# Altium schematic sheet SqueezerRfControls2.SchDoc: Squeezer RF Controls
size C; Organization: LIGO Laboratory; Address1: California Institute of Technology; Address2: Massachusetts Institute of Technology; SheetNumber: 33; SheetTotal: 37; DrawnBy: R.  Abbott; Engineer: R.  Abbott
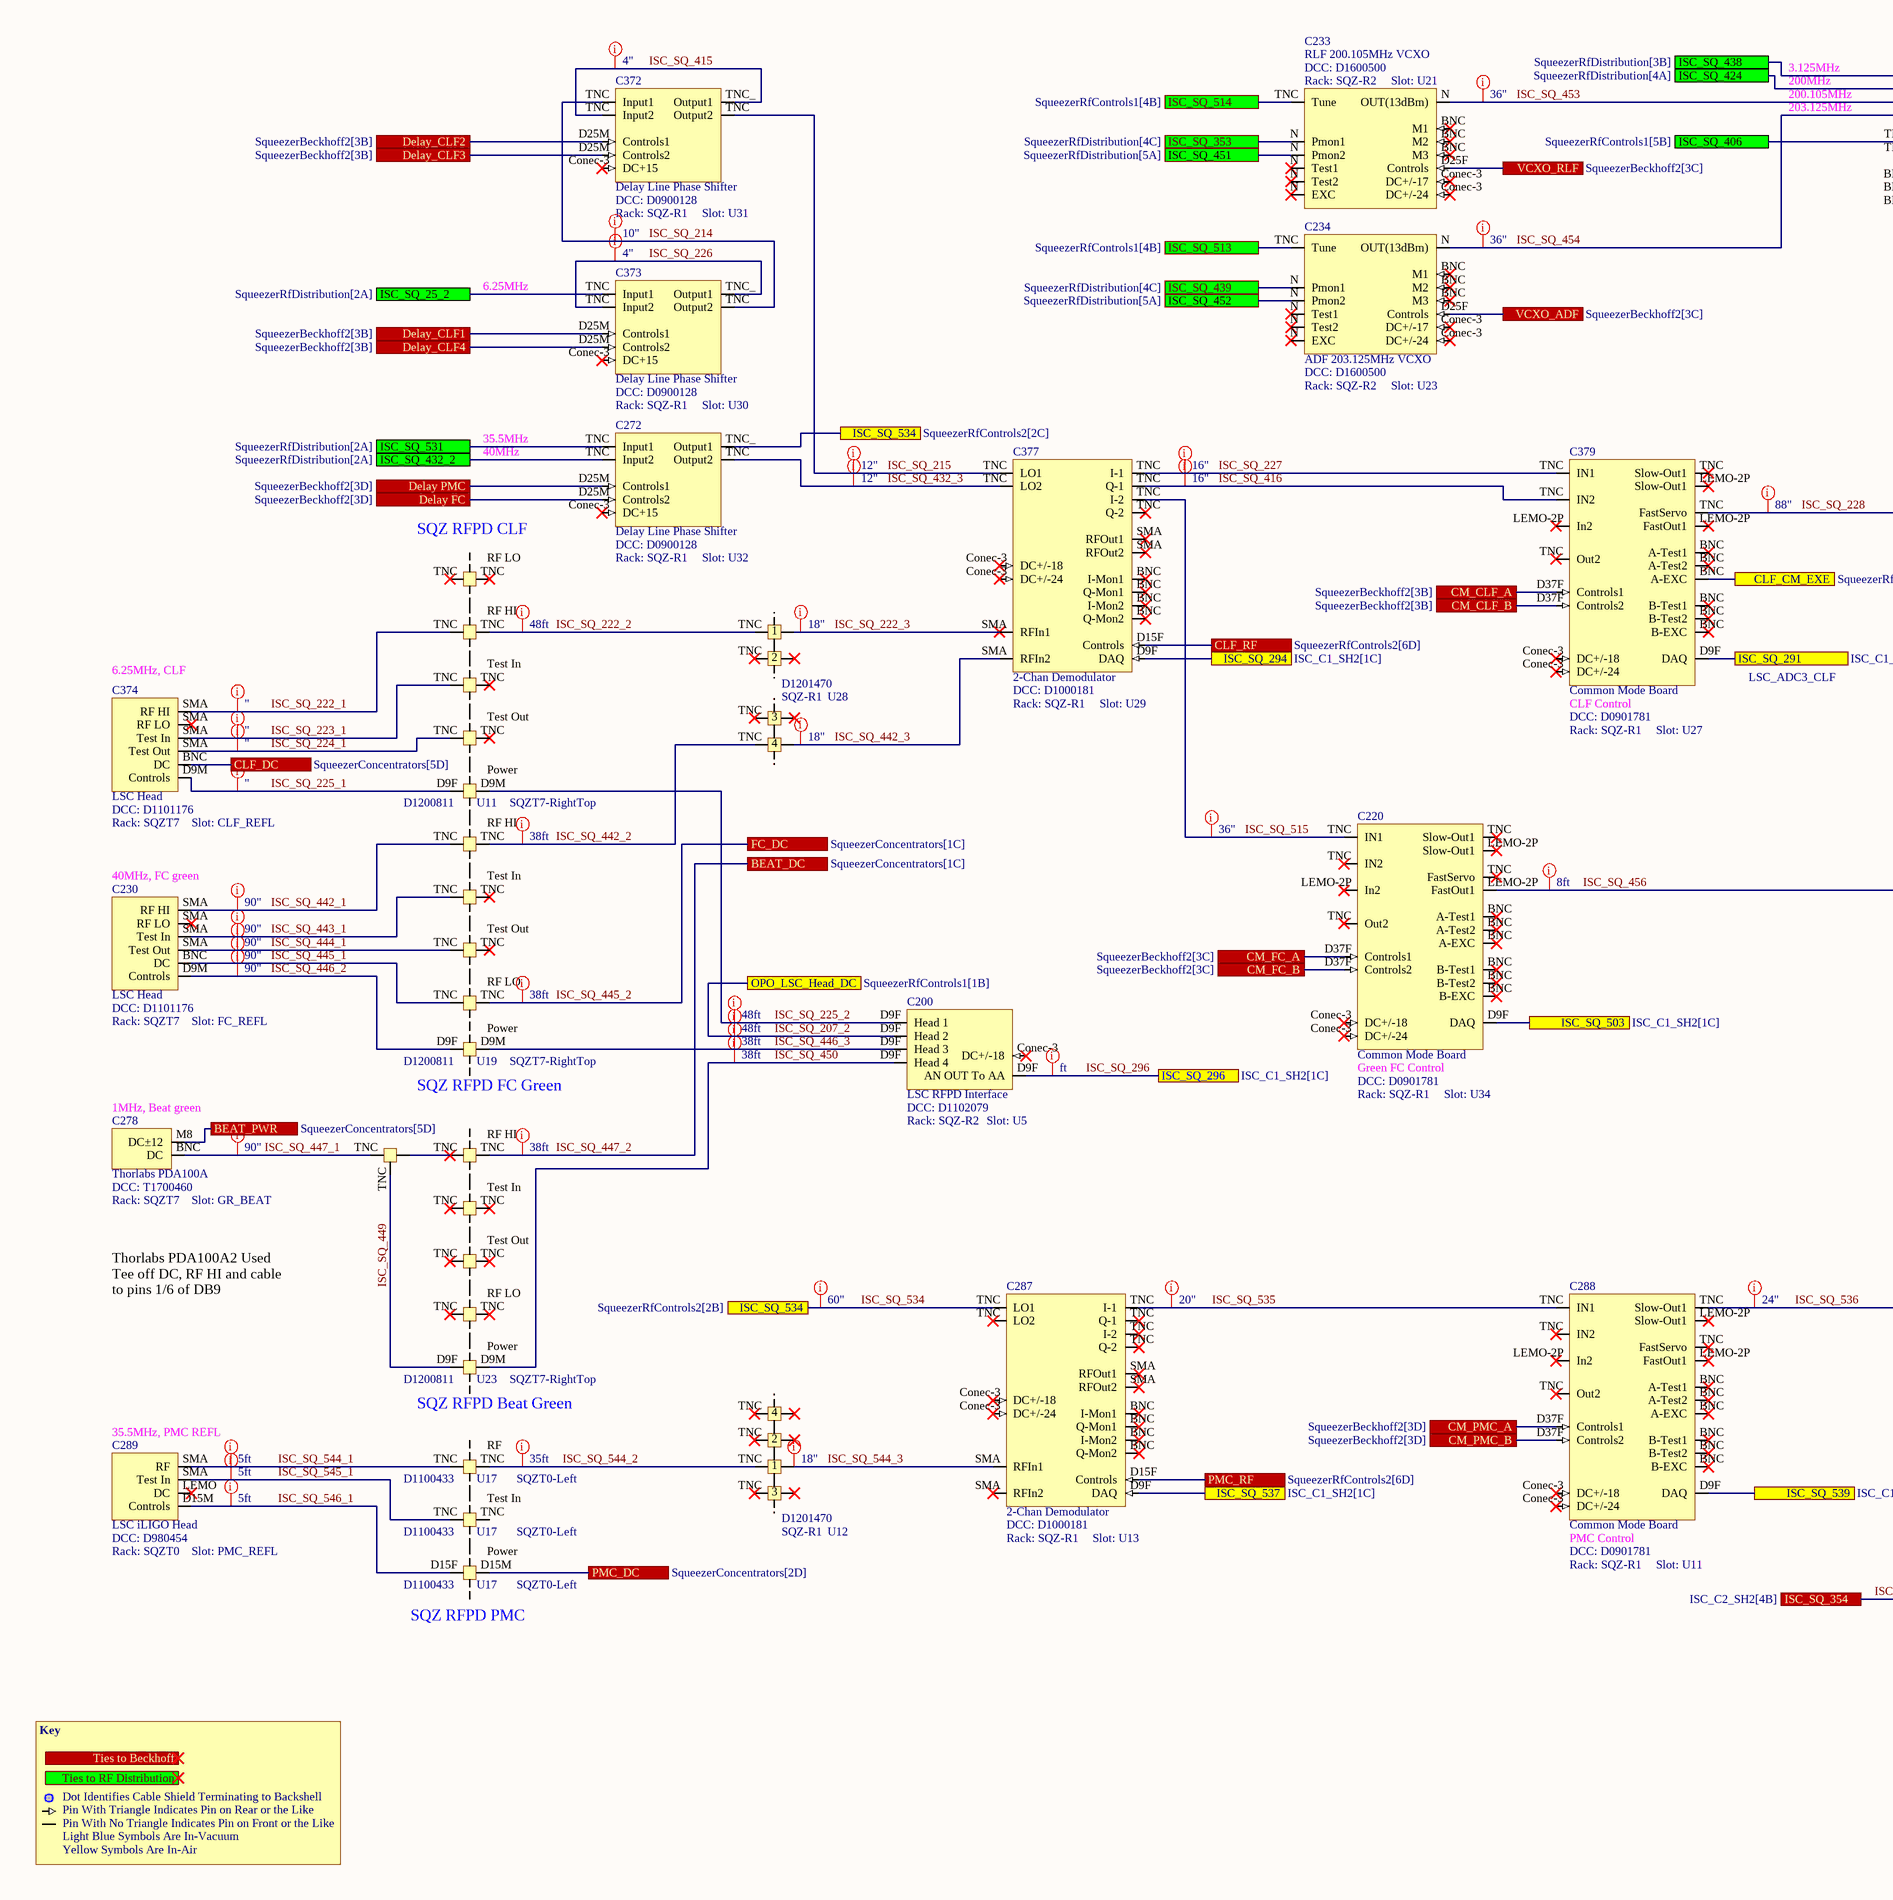
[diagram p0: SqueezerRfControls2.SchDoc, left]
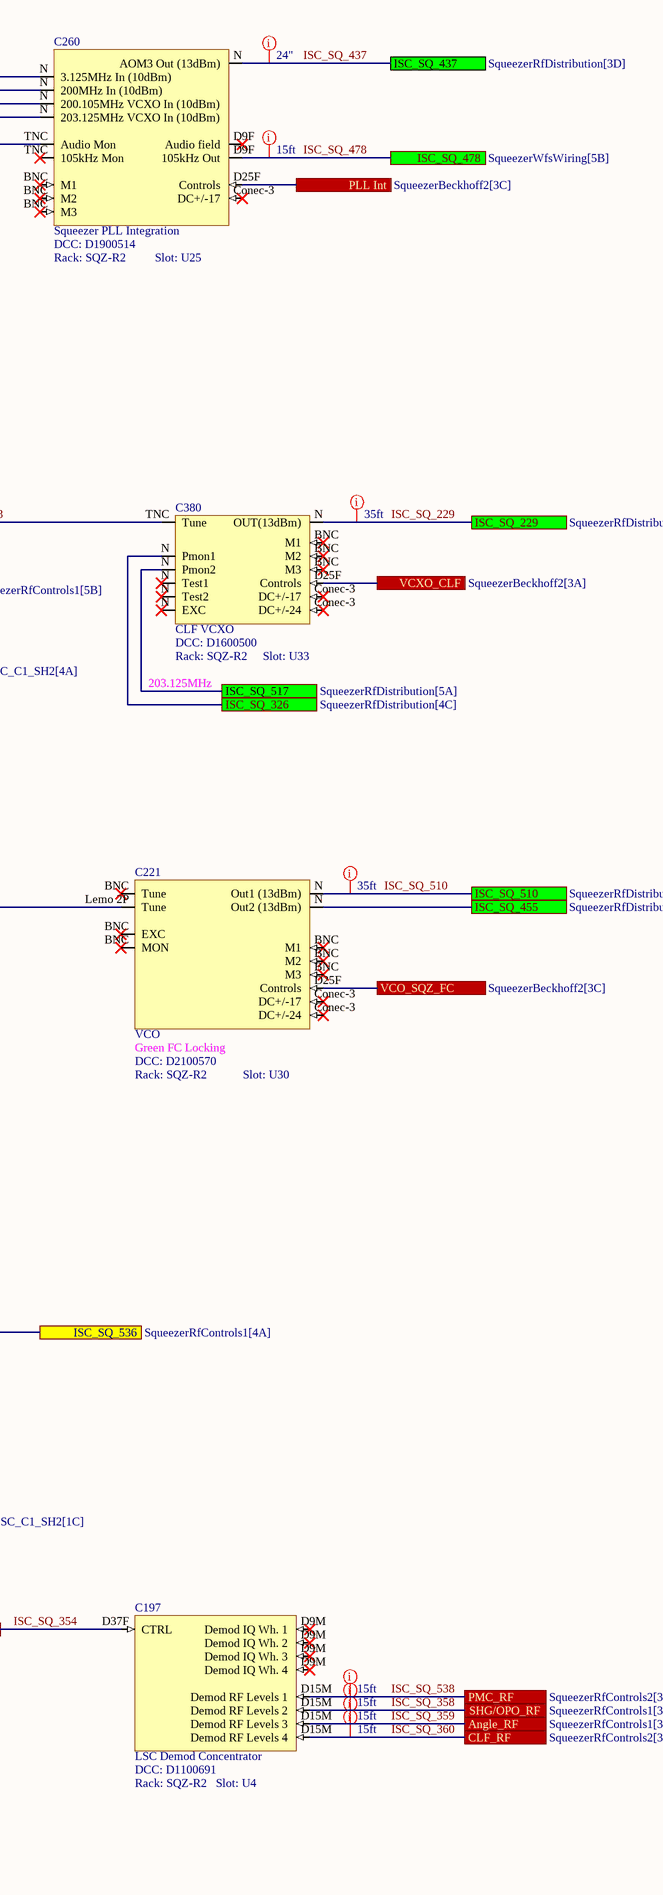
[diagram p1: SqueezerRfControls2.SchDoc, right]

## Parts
(Parts that share a designator on the sheet are numbered #1, #2 ... from top to bottom, then left to right.)
C197  LSC Demod Concentrator  DCC: D1100691  Rack: SQZ-R2  Slot: U4
C200  LSC RFPD Interface  DCC: D1102079  Rack: SQZ-R2  Slot: U5
C220  Common Mode Board  DCC: D0901781  Rack: SQZ-R1  Slot: U34
C221  VCO  DCC: D2100570  Rack: SQZ-R2  Slot: U30
C230  LSC Head  DCC: D1101176  Rack: SQZT7  Slot: FC_REFL
C231  Patch Panel Dual Frequency LSC RFPD  (value not drawn)  (parts A,B,C,D,E of 5)
C233  RLF 200.105MHz VCXO  DCC: D1600500  Rack: SQZ-R2  Slot: U21
C234  ADF 203.125MHz VCXO  DCC: D1600500  Rack: SQZ-R2  Slot: U23
C254  Patch Panel Dual Frequency LSC RFPD  (value not drawn)  (parts A,B,C,D,E of 5)
C260  Squeezer PLL Integration  DCC: D1900514  Rack: SQZ-R2  Slot: U25
C272  Delay Line Phase Shifter  DCC: D0900128  Rack: SQZ-R1  Slot: U32
C278  Thorlabs PDA100A  DCC: T1700460  Rack: SQZT7  Slot: GR_BEAT
C279  Tee  (value not drawn)
C287  2-Chan Demodulator  DCC: D1000181  Rack: SQZ-R1  Slot: U13
C288  Common Mode Board  DCC: D0901781  Rack: SQZ-R1  Slot: U11
C289  LSC iLIGO Head  DCC: D980454  Rack: SQZT0  Slot: PMC_REFL
C290  DCC: D1100433  Rack: SQZT0-Left  Slot: U17  (hidden comment: Patch Panel Legacy iLIGO LSC RFPD)  (parts A,B,C of 3)
C299  Patch Panel TNC 1U  (value not drawn)  (parts A,C of 4)
C372  Delay Line Phase Shifter  DCC: D0900128  Rack: SQZ-R1  Slot: U31
C373  Delay Line Phase Shifter  DCC: D0900128  Rack: SQZ-R1  Slot: U30
C374  LSC Head  DCC: D1101176  Rack: SQZT7  Slot: CLF_REFL
C375  Patch Panel Dual Frequency LSC RFPD  (value not drawn)  (parts A,B,C,D,E of 5)
C376  Patch Panel TNC 1U  (value not drawn)  (parts A,B,C,D of 4)
C377  2-Chan Demodulator  DCC: D1000181  Rack: SQZ-R1  Slot: U29
C379  Common Mode Board  DCC: D0901781  Rack: SQZ-R1  Slot: U27
C380  CLF VCXO  DCC: D1600500  Rack: SQZ-R2  Slot: U33
C?#1  Patch Panel TNC 1U  (value not drawn)  (part D of 4)
C?#2  Patch Panel TNC 1U  (value not drawn)  (part B of 4)

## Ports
Angle_RF (see SqueezerRfControls1[3C]), BEAT_DC (see SqueezerConcentrators[1C]), BEAT_PWR (see SqueezerConcentrators[5D]), CLF_CM_EXE (see SqueezerRfControls1[5B]), CLF_DC (see SqueezerConcentrators[5D]), CLF_RF (see SqueezerRfControls2[3B]), CLF_RF (see SqueezerRfControls2[6D]), CM_CLF_A (see SqueezerBeckhoff2[3B]), CM_CLF_B (see SqueezerBeckhoff2[3B]), CM_FC_A (see SqueezerBeckhoff2[3C]), CM_FC_B (see SqueezerBeckhoff2[3C]), CM_PMC_A (see SqueezerBeckhoff2[3D]), CM_PMC_B (see SqueezerBeckhoff2[3D]), Delay FC (see SqueezerBeckhoff2[3D]), Delay PMC (see SqueezerBeckhoff2[3D]), Delay_CLF1 (see SqueezerBeckhoff2[3B]), Delay_CLF2 (see SqueezerBeckhoff2[3B]), Delay_CLF3 (see SqueezerBeckhoff2[3B]), Delay_CLF4 (see SqueezerBeckhoff2[3B]), FC_DC (see SqueezerConcentrators[1C]), ISC_SQ_25_2 (see SqueezerRfDistribution[2A]), ISC_SQ_229 (see SqueezerRfDistribution[3C]), ISC_SQ_291 (see ISC_C1_SH2[4A]), ISC_SQ_294 (see ISC_C1_SH2[1C]), ISC_SQ_296 (see ISC_C1_SH2[1C]), ISC_SQ_326 (see SqueezerRfDistribution[4C]), ISC_SQ_353 (see SqueezerRfDistribution[4C]), ISC_SQ_354 (see ISC_C2_SH2[4B]), ISC_SQ_406 (see SqueezerRfControls1[5B]), ISC_SQ_424 (see SqueezerRfDistribution[4A]), ISC_SQ_432_2 (see SqueezerRfDistribution[2A]), ISC_SQ_437 (see SqueezerRfDistribution[3D]), ISC_SQ_438 (see SqueezerRfDistribution[3B]), ISC_SQ_439 (see SqueezerRfDistribution[4C]), ISC_SQ_451 (see SqueezerRfDistribution[5A]), ISC_SQ_452 (see SqueezerRfDistribution[5A]), ISC_SQ_455 (see SqueezerRfDistribution[5A]), ISC_SQ_478 (see SqueezerWfsWiring[5B]), ISC_SQ_503 (see ISC_C1_SH2[1C]), ISC_SQ_510 (see SqueezerRfDistribution[3C]), ISC_SQ_513 (see SqueezerRfControls1[4B]), ISC_SQ_514 (see SqueezerRfControls1[4B]), ISC_SQ_517 (see SqueezerRfDistribution[5A]), ISC_SQ_531 (see SqueezerRfDistribution[2A]), ISC_SQ_534 (see SqueezerRfControls2[2B]), ISC_SQ_534 (see SqueezerRfControls2[2C]), ISC_SQ_536 (see SqueezerRfControls1[4A]), ISC_SQ_537 (see ISC_C1_SH2[1C]), ISC_SQ_539 (see ISC_C1_SH2[1C]), OPO_LSC_Head_DC (see SqueezerRfControls1[1B]), PLL Int (see SqueezerBeckhoff2[3C]), PMC_DC (see SqueezerConcentrators[2D]), PMC_RF (see SqueezerRfControls2[3D]), PMC_RF (see SqueezerRfControls2[6D]), SHG/OPO_RF (see SqueezerRfControls1[3B]), Ties to Beckhoff, Ties to RF Distribution, VCO_SQZ_FC (see SqueezerBeckhoff2[3C]), VCXO_ADF (see SqueezerBeckhoff2[3C]), VCXO_CLF (see SqueezerBeckhoff2[3A]), VCXO_RLF (see SqueezerBeckhoff2[3C])

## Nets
BEAT_PWR: C278.M8(DC±12) ; port BEAT_PWR
CLF_CM_EXE: C379.BNC(A-Test1) ; port CLF_CM_EXE
CLF_DC: C374.BNC(DC) ; port CLF_DC
CM_CLF_A: C379.D37F(Controls1) ; port CM_CLF_A
CM_CLF_B: C379.D37F(Controls2) ; port CM_CLF_B
CM_FC_A: C220.D37F(Controls1) ; port CM_FC_A
CM_FC_B: C220.D37F(Controls2) ; port CM_FC_B
CM_PMC_A: C288.D37F(Controls1) ; port CM_PMC_A
CM_PMC_B: C288.D37F(Controls2) ; port CM_PMC_B
Delay FC: C272.D25M(Controls2) ; port Delay FC
Delay PMC: C272.D25M(Controls1) ; port Delay PMC
Delay_CLF1: C373.D25M(Controls1) ; port Delay_CLF1
Delay_CLF2: C372.D25M(Controls1) ; port Delay_CLF2
Delay_CLF3: C372.D25M(Controls2) ; port Delay_CLF3
Delay_CLF4: C373.D25M(Controls2) ; port Delay_CLF4
ISC_SQ_25_2: C373.TNC(Input1) ; port ISC_SQ_25_2
ISC_SQ_207_2: C200.D9F(Head_2) ; port OPO_LSC_Head_DC
ISC_SQ_214: C372.TNC(Input1) C373.TNC(Output2)
ISC_SQ_215: C372.TNC(Output2) C377.TNC(LO1)
ISC_SQ_222_1: C374.SMA(RF_HI) C375.TNC(RFLO)
ISC_SQ_222_2: C375.TNC(RFHI) C376.TNC
ISC_SQ_222_3: C376.TNC C377.SMA(RFOut1)
ISC_SQ_223_1: C374.SMA(Test_In) C375.TNC(TestIn)
ISC_SQ_224_1: C374.SMA(Test_Out) C375.TNC(TestOut)
ISC_SQ_225_1: C374.D9M(Controls) C375.D9F(Power)
ISC_SQ_225_2: C200.D9F(Head_1) C375.D9M(Power)
ISC_SQ_226: C373.TNC(Input2) C373.TNC_(Output1)
ISC_SQ_227: C377.TNC(I-1) C379.TNC(IN1)
ISC_SQ_228: C379.TNC(FastServo) C380.TNC(Tune)
ISC_SQ_229: C380.N(OUT(13dBm)) ; port ISC_SQ_229
ISC_SQ_291: C379.D9F(DAQ) ; port ISC_SQ_291
ISC_SQ_294: C377.D9F(DAQ) ; port ISC_SQ_294
ISC_SQ_296: C200.D9F(AN_OUT_To_AA) ; port ISC_SQ_296
ISC_SQ_326: C380.N(Pmon1) ; port ISC_SQ_326
ISC_SQ_353: C233.N(Pmon1) ; port ISC_SQ_353
ISC_SQ_354: C197.D37F(CTRL) ; port ISC_SQ_354
ISC_SQ_358: C197.D15M(Demod_RF_Levels_2) ; port SHG/OPO_RF
ISC_SQ_359: C197.D15M(Demod_RF_Levels_3) ; port Angle_RF
ISC_SQ_360: C197.D15M(Demod_RF_Levels_4) C377.D15F(Controls) ; port CLF_RF
ISC_SQ_406: C260.TNC(Audio_Mon) ; port ISC_SQ_406
ISC_SQ_415: C372.TNC(Input2) C372.TNC_(Output1)
ISC_SQ_416: C377.TNC(Q-1) C379.TNC(IN2)
ISC_SQ_424: C260.N(200MHz_In_(10dBm)) ; port ISC_SQ_424
ISC_SQ_432_2: C272.TNC(Input2) ; port ISC_SQ_432_2
ISC_SQ_432_3: C272.TNC(Output2) C377.TNC(LO2)
ISC_SQ_437: C260.N(AOM3_Out_(13dBm)) ; port ISC_SQ_437
ISC_SQ_438: C260.N(3.125MHz_In_(10dBm)) ; port ISC_SQ_438
ISC_SQ_439: C234.N(Pmon1) ; port ISC_SQ_439
ISC_SQ_442_1: C230.SMA(RF_HI) C231.TNC(RFHI)
ISC_SQ_442_2: C231.TNC(RFHI) C376.TNC
ISC_SQ_442_3: C376.TNC C377.SMA(RFIn2)
ISC_SQ_443_1: C230.SMA(Test_In) C231.TNC(TestIn)
ISC_SQ_444_1: C230.SMA(Test_Out) C231.TNC(TestOut)
ISC_SQ_445_1: C230.BNC(DC) C231.TNC(RFLO)
ISC_SQ_445_2: C231.TNC(RFLO) ; port FC_DC
ISC_SQ_446_2: C230.D9M(Controls) C231.D9F(Power)
ISC_SQ_446_3: C200.D9F(Head_3) C231.D9M(Power)
ISC_SQ_447_1: C278.BNC(DC) C279.TNC
ISC_SQ_447_2: C254.TNC(RFHI) ; port BEAT_DC
ISC_SQ_449: C254.D9F(Power) C279.TNC
ISC_SQ_450: C200.D9F(Head_4) C254.D9M(Power)
ISC_SQ_451: C233.N(Pmon2) ; port ISC_SQ_451
ISC_SQ_452: C234.N(Pmon2) ; port ISC_SQ_452
ISC_SQ_453: C233.N(OUT(13dBm)) C260.N(200.105MHz_VCXO_In_(10dBm))
ISC_SQ_454: C234.N(OUT(13dBm)) C260.N(203.125MHz_VCXO_In_(10dBm))
ISC_SQ_455: C221.N(Out2_(13dBm)) ; port ISC_SQ_455
ISC_SQ_456: C220.LEMO-2P(In2) C221.Lemo_2P(Tune)
ISC_SQ_478: C260.D9F(105kHz_Out) ; port ISC_SQ_478
ISC_SQ_503: C220.D9F(DAQ) ; port ISC_SQ_503
ISC_SQ_510: C221.N(Out1_(13dBm)) ; port ISC_SQ_510
ISC_SQ_513: C234.TNC(Tune) ; port ISC_SQ_513
ISC_SQ_514: C233.TNC(Tune) ; port ISC_SQ_514
ISC_SQ_515: C220.TNC(IN1) C377.TNC(I-2)
ISC_SQ_517: C380.N(Pmon2) ; port ISC_SQ_517
ISC_SQ_531: C272.TNC(Input1) ; port ISC_SQ_531
ISC_SQ_534: C272.TNC_(Output1) C287.TNC(LO1) ; port ISC_SQ_534
ISC_SQ_535: C287.TNC(I-1) C288.TNC(IN1)
ISC_SQ_536: C288.TNC(Slow-Out1) ; port ISC_SQ_536
ISC_SQ_537: C287.D9F(DAQ) ; port ISC_SQ_537
ISC_SQ_538: C197.D15M(Demod_RF_Levels_1) C287.D15F(Controls) ; port PMC_RF
ISC_SQ_539: C288.D9F(DAQ) ; port ISC_SQ_539
ISC_SQ_544_1: C289.SMA(RF) C290.TNC(RFHI)
ISC_SQ_544_2: C290.TNC(RFHI) C299.TNC
ISC_SQ_544_3: C287.SMA(RFOut1) C299.TNC
ISC_SQ_545_1: C289.SMA(Test_In) C290.TNC(TestIn)
ISC_SQ_546_1: C289.D15M(Controls) C290.D15F(Power)
PLL Int: C260.D25F(Controls) ; port PLL Int
PMC_DC: C290.D15M(Power) ; port PMC_DC
VCO_SQZ_FC: C221.D25F(Controls) ; port VCO_SQZ_FC
VCXO_ADF: C234.D25F(Controls) ; port VCXO_ADF
VCXO_CLF: C380.D25F(Controls) ; port VCXO_CLF
VCXO_RLF: C233.D25F(Controls) ; port VCXO_RLF
NetC254_TNC: C254.TNC(RFLO) C279.TNC

Not connected (* = marked no-connect by the designer): C197 D9M(Demod_IQ_Wh._1)*; C200 Conec-3(DC+/-18)*; C220 BNC(A-Test1)* Conec-3(DC+/-18)*; C221 BNC(Tune)* Conec-3(DC+/-17)*; C233 BNC(M1)* Conec-3(DC+/-17)*; C234 BNC(M1)* Conec-3(DC+/-17)*; C260 BNC(M1)* Conec-3(DC+/-17)*; C272 Conec-3(DC+15)*; C287 BNC(I-Mon1)* Conec-3(DC+/-18)*; C288 BNC(A-Test1)* Conec-3(DC+/-18)* LEMO-2P(In2)*; C289 LEMO(DC)*; C372 Conec-3(DC+15)*; C373 Conec-3(DC+15)*; C377 BNC(I-Mon1)* Conec-3(DC+/-18)*; C379 Conec-3(DC+/-18)* LEMO-2P(In2)*; C380 BNC(M1)* Conec-3(DC+/-17)*; C?#1 TNC(4)*; C?#2 TNC(2)*

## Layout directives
Length: ": ISC_SQ_222_1, ISC_SQ_223_1, ISC_SQ_224_1, ISC_SQ_225_1
Length: 48ft: ISC_SQ_207_2, ISC_SQ_222_2, ISC_SQ_225_2
Length: 16": ISC_SQ_227, ISC_SQ_416
Length: 88": ISC_SQ_228
Length: 35ft: ISC_SQ_229, ISC_SQ_510, ISC_SQ_544_2
Length: 10": ISC_SQ_214
Length: 4": ISC_SQ_226, ISC_SQ_415
Length: 18": ISC_SQ_222_3, ISC_SQ_442_3, ISC_SQ_544_3
Length: 12": ISC_SQ_215, ISC_SQ_432_3
Length: 90": ISC_SQ_442_1, ISC_SQ_443_1, ISC_SQ_444_1, ISC_SQ_445_1, ISC_SQ_446_2, ISC_SQ_447_1
Length: 38ft: ISC_SQ_442_2, ISC_SQ_445_2, ISC_SQ_446_3, ISC_SQ_447_2, ISC_SQ_450
Length: ft: ISC_SQ_296
Length: 8ft: ISC_SQ_456
Length: 36": ISC_SQ_453, ISC_SQ_454, ISC_SQ_515
Length: 15ft: ISC_SQ_358, ISC_SQ_359, ISC_SQ_360, ISC_SQ_478, ISC_SQ_538
Length: 24": ISC_SQ_437, ISC_SQ_536
Length: 5ft: ISC_SQ_544_1, ISC_SQ_545_1, ISC_SQ_546_1
Length: 60": ISC_SQ_534
Length: 20": ISC_SQ_535

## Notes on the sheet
- 200MHz
- 3.125MHz
- 200.105MHz
- 203.125MHz
- 6.25MHz
- 40MHz
- 35.5MHz
- (near C375) SQZ RFPD CLF
- (near C374) 6.25MHz, CLF
- LSC_ADC3_CLF
- (near C379) CLF Control
- (near C230) 40MHz, FC green
- (near C220) Green FC Control
- (near C221) Green FC Locking
- (near C278) 1MHz, Beat green
- (near C231) SQZ RFPD FC Green
- Thorlabs PDA100A2 Used
  Tee off DC, RF HI and cable
  to pins 1/6 of DB9
- (near C254) SQZ RFPD Beat Green
- (near C289) 35.5MHz, PMC REFL
- (near C288) PMC Control
- (near C290) SQZ RFPD PMC
- Key
- Dot Identifies Cable Shield Terminating to Backshell
- Pin With Triangle Indicates Pin on Rear or the Like
- Pin With No Triangle Indicates Pin on Front or the Like
- Light Blue Symbols Are In-Vacuum
- Yellow Symbols Are In-Air

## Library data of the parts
C197 = LSC Demod Concentrator: Serial: Sxxxxxxx; System: ISC
C200 = LSC RFPD Interface: Serial: Sxxxxxxx; System: ISC
C220 C288 C379 = CommonModeBoard: Serial: Sxxxxxxx; System: ISC
C221 = VCONew: New VCO; Serial: Sxxxxxxx; System: ISC
C230 C374 = LSC Head: Serial: Sxxxxxxx; System: ISC
C231 = Patch Panel Dual Frequency LSC RFPD: Patch Panel (D1200811); Serial: Sxxxxxxx; System: ISC; Rack: SQZT7-RightTop; Slot: U19
C233 C234 C380 = VCXO: Serial: Sxxxxxxx; System: ISC
C254 = Patch Panel Dual Frequency LSC RFPD: Patch Panel (D1200811); Serial: Sxxxxxxx; System: ISC; Rack: SQZT7-RightTop; Slot: U23
C260 = Squeezer PLL: Serial: Sxxxxxxx; System: ISC
C272 C372 C373 = DelayLinePhaseShifter: Serial: Sxxxxxxx; System: ISC
C278 = Thorlabs PDA100A: Serial: Sxxxxxxx; System: ISC
C279 = TNC Tee: Tee (TNC); Serial: Sxxxxxxx; System: ISC; Rack: SQZT7; Slot: U?
C287 C377 = 2-Chan Demod: Serial: Sxxxxxxx; System: ISC
C289 = LSC Legacy Head: LSC iLIGO Legacy Head; Serial: Sxxxxxxx; System: ISC
C290 = Patch Panel Legacy LSC RFPD: Patch Panel (D1100433); Serial: Sxxxxxxx; System: ISC
C299 C?#1 C?#2 = Patch Panel TNC 1U: Patch Panel (D1201470); Serial: Sxxxxxxx; System: ISC; Rack: SQZ-R1; Slot: U12
C375 = Patch Panel Dual Frequency LSC RFPD: Patch Panel (D1200811); Serial: Sxxxxxxx; System: ISC; Rack: SQZT7-RightTop; Slot: U11
C376 = Patch Panel TNC 1U: Patch Panel (D1201470); Serial: Sxxxxxxx; System: ISC; Rack: SQZ-R1; Slot: U28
